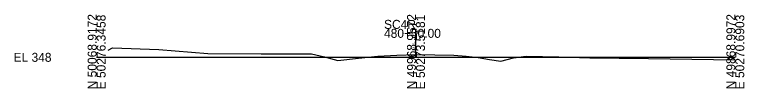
# Model space of a CAD drawing. Extents: x 7498 to 13027, y 90095 to 109625.
# Drawn here: x 7498.3 to 7726.8, y 90595.5 to 90618.5 of the extents above; entities that cross this region are included whole.
import ezdxf

# ---------------------------------------------------------------- set-up
doc = ezdxf.new("R2010")
doc.units = 0
for name, color, linetype in [('Level 10', 7, 'Continuous'), ('Level 60', 7, 'Continuous'), ('Level 63', 7, 'Continuous')]:
    doc.layers.add(name, color=color, linetype=linetype)

msp = doc.modelspace()

# ---------------------------------------------------------------- linework, layer by layer
at = {"layer": 'Level 60'}
for p, q in [((7527.59, 90607.43), (7528.94, 90608.12)), ((7528.94, 90608.12), (7543.51, 90607.63)), ((7543.51, 90607.63), (7558.85, 90606.31)), ((7558.85, 90606.31), (7575.5, 90606.22)), ((7575.5, 90606.22), (7591.25, 90606.21)), ((7591.25, 90606.21), (7595.39, 90605.27)), ((7595.39, 90605.27), (7599.51, 90604.21)), ((7599.51, 90604.21), (7605.97, 90604.92)), ((7605.97, 90604.92), (7612.07, 90605.53)), ((7612.07, 90605.53), (7617.97, 90605.8)), ((7617.97, 90605.8), (7623.99, 90606.09)), ((7623.99, 90606.09), (7629.88, 90605.97)), ((7629.88, 90605.97), (7635.89, 90605.87)), ((7635.89, 90605.87), (7639.68, 90605.49)), ((7639.68, 90605.49), (7643.51, 90605.15)), ((7643.51, 90605.15), (7647.05, 90604.49)), ((7647.05, 90604.49), (7650.51, 90604)), ((7650.51, 90604), (7654.57, 90604.96)), ((7654.57, 90604.96), (7658.5, 90605.55)), ((7658.5, 90605.55), (7668.77, 90605.3)), ((7668.77, 90605.3), (7678.47, 90605.01)), ((7678.47, 90605.01), (7696.83, 90604.75)), ((7696.83, 90604.75), (7723.99, 90604.42))]:
    msp.add_line(p, q, dxfattribs=at)
at = {"layer": 'Level 63'}
for p, q in [((7623.99, 90605.16), (7623.99, 90614.05)), ((7523.99, 90605.16), (7623.99, 90605.16)), ((7623.99, 90605.16), (7723.99, 90605.16))]:
    msp.add_line(p, q, dxfattribs=at)

# ---------------------------------------------------------------- texts
at = {"layer": 'Level 10'}
msp.add_text('348.93', height=0.6, rotation=90, dxfattribs=at).set_placement((7623.59, 90607.09))
at = {"layer": 'Level 63'}
for s, p in [('N 50068.9172', (7523.99, 90595.16)), ('E 50276.3458', (7526.79, 90595.16)), ('N 49968.9572', (7623.99, 90595.16)), ('E 50273.5181', (7626.79, 90595.16)), ('N 49868.9972', (7723.99, 90595.16)), ('E 50270.6903', (7726.79, 90595.16))]:
    msp.add_text(s, height=2.8, rotation=90, dxfattribs=at).set_placement(p)
for s, p in [('SC4R', (7613.99, 90614.05)), ('480+50.00', (7613.99, 90611.25)), ('EL 348', (7497.99, 90603.76))]:
    msp.add_text(s, height=2.8, dxfattribs=at).set_placement(p)

doc.saveas('drawing.dxf')
